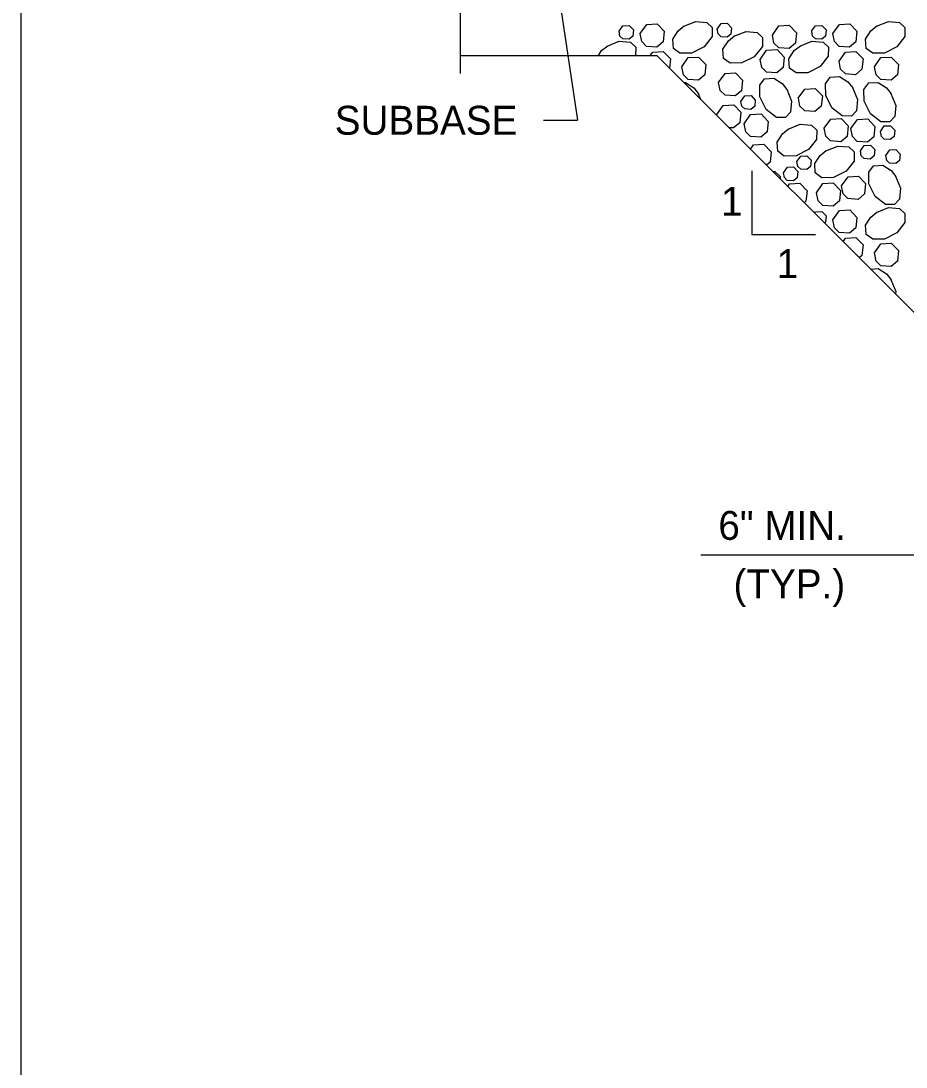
# Model space of a CAD drawing. Extents: x 638079 to 640019, y 297691 to 298879.
# Drawn here: x 639154 to 639245.9, y 298633.1 to 298741.7 of the extents above; entities that cross this region are included whole.
import ezdxf

# ---------------------------------------------------------------- set-up
doc = ezdxf.new("R2010")
doc.units = 0
doc.layers.add('1', color=7, linetype='Continuous')

msp = doc.modelspace()

# ---------------------------------------------------------------- linework, layer by layer
at = {"layer": '1'}
for p, q in [((639199.6, 298780.56), (639199.6, 298736.22)), ((639209.3, 298748.11), (639211.77, 298731.39)), ((639199.6, 298738.08), (639220.02, 298738.08)), ((639250.5, 298707.6), (639220.02, 298738.08)), ((639208.25, 298731.39), (639211.77, 298731.39)), ((639229.88, 298726.11), (639229.88, 298719.52)), ((639229.88, 298719.52), (639236.47, 298719.52)), ((639224.58, 298686.26), (639418.14, 298686.26))]:
    msp.add_line(p, q, dxfattribs=at)
for points in [[(639940.03, 298300.23), (639940.03, 298864.23), (639154.03, 298864.23), (639154.03, 298300.23), (639940.03, 298300.23), (639940.03, 298326.59), (639740.03, 298326.59), (639740.03, 298391.26), (639940.03, 298391.26), (639940.03, 298420.23), (639740.03, 298420.23), (639740.03, 298300.23), (639818.83, 298300.23), (639818.83, 298326.59), (639818.83, 298300.23), (639895.83, 298300.23), (639895.83, 298326.59), (639895.83, 298314.27), (639940.03, 298314.27)], [(639216.09, 298740.61), (639216.49, 298741.18), (639217.13, 298741.22), (639217.58, 298740.75), (639217.52, 298740.1), (639217.12, 298739.77), (639216.48, 298739.82), (639216.18, 298740.11), (639216.09, 298740.61)], [(639218.29, 298740.36), (639218.96, 298741.32), (639220.04, 298741.38), (639220.78, 298740.6), (639220.67, 298739.52), (639220.01, 298738.97), (639218.95, 298739.04), (639218.45, 298739.53), (639218.29, 298740.36)], [(639222.8, 298741.12), (639224.06, 298741.62), (639225.21, 298741.52), (639225.76, 298741), (639225.75, 298740.06), (639224.91, 298739), (639223.62, 298738.35), (639222.41, 298738.33), (639221.73, 298738.82), (639221.66, 298739.78), (639222.22, 298740.65), (639222.85, 298741.16)], [(639226.27, 298740.83), (639226.67, 298741.4), (639227.32, 298741.44), (639227.77, 298740.97), (639227.7, 298740.32), (639227.3, 298739.99), (639226.67, 298740.04), (639226.37, 298740.33), (639226.27, 298740.83)], [(639232, 298740.21), (639232.67, 298741.17), (639233.74, 298741.23), (639234.49, 298740.46), (639234.38, 298739.37), (639233.72, 298738.82), (639232.66, 298738.9), (639232.16, 298739.38), (639232, 298740.21)], [(639236.07, 298740.61), (639236.48, 298741.18), (639237.12, 298741.22), (639237.57, 298740.75), (639237.51, 298740.1), (639237.11, 298739.77), (639236.47, 298739.82), (639236.17, 298740.11), (639236.08, 298740.61)], [(639238.28, 298740.36), (639238.95, 298741.32), (639240.02, 298741.38), (639240.77, 298740.6), (639240.66, 298739.52), (639240, 298738.97), (639238.94, 298739.04), (639238.44, 298739.53), (639238.28, 298740.36)], [(639242.79, 298741.12), (639244.05, 298741.62), (639245.2, 298741.52), (639245.75, 298741), (639245.73, 298740.06), (639244.9, 298739), (639243.61, 298738.35), (639242.4, 298738.33), (639241.72, 298738.82), (639241.65, 298739.78), (639242.21, 298740.65), (639242.84, 298741.16)], [(639228.01, 298740.09), (639229.27, 298740.59), (639230.43, 298740.49), (639230.97, 298739.97), (639230.96, 298739.03), (639230.12, 298737.96), (639228.84, 298737.32), (639227.62, 298737.3), (639226.94, 298737.79), (639226.87, 298738.75), (639227.43, 298739.62), (639228.06, 298740.12)], [(639213.94, 298738.08), (639214.27, 298738.6), (639214.91, 298739.11)], [(639214.86, 298739.07), (639216.11, 298739.57), (639217.27, 298739.47), (639217.82, 298738.95), (639217.8, 298738.08)], [(639234.85, 298739.07), (639236.1, 298739.57), (639237.26, 298739.47), (639237.81, 298738.95), (639237.79, 298738.01), (639236.96, 298736.95), (639235.67, 298736.3), (639234.45, 298736.28), (639233.77, 298736.77), (639233.71, 298737.74), (639234.26, 298738.6), (639234.9, 298739.11)], [(639219.33, 298738.08), (639219.59, 298738.45), (639220.67, 298738.51), (639221.41, 298737.74), (639221.32, 298736.78)], [(639222.6, 298736.91), (639223.27, 298737.87), (639224.34, 298737.93), (639225.09, 298737.15), (639224.98, 298736.07), (639224.32, 298735.52), (639223.26, 298735.6), (639222.76, 298736.08), (639222.6, 298736.91)], [(639230.73, 298737.68), (639231.4, 298738.64), (639232.48, 298738.7), (639233.22, 298737.93), (639233.11, 298736.84), (639232.45, 298736.29), (639231.39, 298736.37), (639230.89, 298736.85), (639230.73, 298737.68)], [(639238.91, 298737.5), (639239.58, 298738.45), (639240.66, 298738.51), (639241.4, 298737.74), (639241.29, 298736.66), (639240.63, 298736.1), (639239.57, 298736.18), (639239.07, 298736.66), (639238.91, 298737.5)], [(639242.59, 298736.91), (639243.26, 298737.87), (639244.33, 298737.93), (639245.08, 298737.15), (639244.97, 298736.07), (639244.31, 298735.52), (639243.25, 298735.6), (639242.75, 298736.08), (639242.59, 298736.91)], [(639226.42, 298735.28), (639227.09, 298736.24), (639228.17, 298736.3), (639228.91, 298735.53), (639228.8, 298734.44), (639228.14, 298733.89), (639227.08, 298733.97), (639226.58, 298734.45), (639226.42, 298735.28)], [(639233.48, 298734.61), (639233.98, 298733.35), (639233.88, 298732.2), (639233.35, 298731.65), (639232.42, 298731.66), (639231.35, 298732.5), (639230.71, 298733.79), (639230.69, 298735), (639231.17, 298735.68), (639232.14, 298735.75), (639233, 298735.19), (639233.51, 298734.56)], [(639240.31, 298734.77), (639240.81, 298733.51), (639240.71, 298732.36), (639240.19, 298731.81), (639239.25, 298731.83), (639238.18, 298732.66), (639237.54, 298733.95), (639237.52, 298735.16), (639238, 298735.85), (639238.97, 298735.91), (639239.84, 298735.36), (639240.34, 298734.72)], [(639222.81, 298735.29), (639222.97, 298735.3), (639223.83, 298734.75), (639224.34, 298734.11)], [(639234.68, 298733.66), (639235.36, 298734.61), (639236.43, 298734.67), (639237.18, 298733.9), (639237.07, 298732.82), (639236.41, 298732.27), (639235.35, 298732.34), (639234.85, 298732.83), (639234.69, 298733.66)], [(639244.3, 298734.16), (639244.79, 298732.9), (639244.69, 298731.75), (639244.17, 298731.2), (639243.23, 298731.22), (639242.17, 298732.05), (639241.53, 298733.34), (639241.5, 298734.55), (639241.99, 298735.24), (639242.96, 298735.3), (639243.82, 298734.75), (639244.33, 298734.11)], [(639224.31, 298734.16), (639224.55, 298733.54)], [(639228.73, 298733.32), (639229.13, 298733.9), (639229.78, 298733.94), (639230.22, 298733.47), (639230.16, 298732.82), (639229.76, 298732.49), (639229.13, 298732.54), (639228.83, 298732.83), (639228.73, 298733.32)], [(639226.23, 298731.96), (639226.9, 298732.92), (639227.98, 298732.98), (639228.72, 298732.21), (639228.62, 298731.12), (639227.95, 298730.57), (639227.49, 298730.6)], [(639226.26, 298731.84), (639226.23, 298731.96)], [(639229.07, 298731.01), (639229.74, 298731.97), (639230.82, 298732.03), (639231.56, 298731.26), (639231.46, 298730.17), (639230.79, 298729.62), (639229.73, 298729.7), (639229.23, 298730.18), (639229.07, 298731.01)], [(639237.38, 298730.54), (639238.05, 298731.5), (639239.12, 298731.56), (639239.87, 298730.78), (639239.76, 298729.7), (639239.1, 298729.15), (639238.04, 298729.22), (639237.54, 298729.71), (639237.38, 298730.54)], [(639240.14, 298730.5), (639240.81, 298731.46), (639241.89, 298731.52), (639242.63, 298730.74), (639242.52, 298729.66), (639241.86, 298729.11), (639240.8, 298729.18), (639240.3, 298729.67), (639240.14, 298730.5)], [(639233.63, 298730.45), (639234.88, 298730.95), (639236.04, 298730.85), (639236.59, 298730.33), (639236.57, 298729.39), (639235.74, 298728.33), (639234.45, 298727.68), (639233.23, 298727.66), (639232.55, 298728.15), (639232.49, 298729.11), (639233.04, 298729.98), (639233.68, 298730.48)], [(639243.2, 298730.2), (639243.6, 298730.78), (639244.25, 298730.81), (639244.69, 298730.35), (639244.63, 298729.7), (639244.23, 298729.37), (639243.6, 298729.41), (639243.3, 298729.7), (639243.2, 298730.2)], [(639229.73, 298728.37), (639230.04, 298728.82), (639231.12, 298728.88), (639231.86, 298728.11), (639231.76, 298727.03), (639231.38, 298726.72)], [(639237.53, 298728.21), (639238.78, 298728.7), (639239.94, 298728.6), (639240.49, 298728.08), (639240.47, 298727.14), (639239.64, 298726.08), (639238.35, 298725.44), (639237.14, 298725.41), (639236.45, 298725.9), (639236.39, 298726.87), (639236.94, 298727.73), (639237.58, 298728.24)], [(639241.12, 298728.19), (639241.52, 298728.76), (639242.17, 298728.8), (639242.61, 298728.33), (639242.55, 298727.68), (639242.15, 298727.35), (639241.52, 298727.4), (639241.22, 298727.69), (639241.12, 298728.19)], [(639243.77, 298727.71), (639244.17, 298728.29), (639244.81, 298728.32), (639245.26, 298727.86), (639245.2, 298727.21), (639244.8, 298726.88), (639244.16, 298726.92), (639243.86, 298727.21), (639243.77, 298727.71)], [(639234.53, 298727.08), (639234.93, 298727.66), (639235.58, 298727.69), (639236.03, 298727.23), (639235.96, 298726.58), (639235.56, 298726.25), (639234.93, 298726.29), (639234.63, 298726.58), (639234.53, 298727.08)], [(639232.03, 298726.06), (639232.25, 298726.04), (639232.8, 298725.52), (639232.8, 298725.3)], [(639233.14, 298725.92), (639233.55, 298726.49), (639234.19, 298726.53), (639234.64, 298726.06), (639234.57, 298725.41), (639234.18, 298725.08), (639233.54, 298725.13), (639233.24, 298725.42), (639233.14, 298725.92)], [(639244.78, 298725.58), (639245.28, 298724.32), (639245.18, 298723.17), (639244.66, 298722.62), (639243.72, 298722.64), (639242.66, 298723.47), (639242.01, 298724.76), (639241.99, 298725.97), (639242.48, 298726.65), (639243.44, 298726.72), (639244.31, 298726.16), (639244.82, 298725.53)], [(639233.59, 298724.51), (639233.77, 298724.77), (639234.84, 298724.83), (639235.59, 298724.06), (639235.48, 298722.97), (639235.29, 298722.81)], [(639236.57, 298723.85), (639237.24, 298724.81), (639238.31, 298724.87), (639239.06, 298724.1), (639238.95, 298723.01), (639238.29, 298722.46), (639237.23, 298722.54), (639236.73, 298723.02), (639236.57, 298723.85)], [(639239.17, 298724.56), (639239.85, 298725.51), (639240.92, 298725.57), (639241.67, 298724.8), (639241.56, 298723.72), (639240.89, 298723.16), (639239.84, 298723.24), (639239.34, 298723.72), (639239.17, 298724.56)], [(639236.38, 298721.72), (639236.48, 298721.87), (639237.12, 298721.9), (639237.57, 298721.44), (639237.51, 298720.79), (639237.4, 298720.7)], [(639238.28, 298721.04), (639238.95, 298722), (639240.02, 298722.06), (639240.77, 298721.29), (639240.66, 298720.2), (639240, 298719.65), (639238.94, 298719.73), (639238.44, 298720.21), (639238.28, 298721.04)], [(639242.79, 298721.81), (639244.05, 298722.31), (639245.2, 298722.21), (639245.75, 298721.69), (639245.73, 298720.75), (639244.9, 298719.68), (639243.61, 298719.04), (639242.4, 298719.02), (639241.72, 298719.5), (639241.65, 298720.47), (639242.21, 298721.33), (639242.84, 298721.84)], [(639239.33, 298718.77), (639239.58, 298719.14), (639240.66, 298719.2), (639241.4, 298718.43), (639241.29, 298717.34), (639241, 298717.1)], [(639242.59, 298717.6), (639243.26, 298718.55), (639244.33, 298718.61), (639245.08, 298717.84), (639244.97, 298716.76), (639244.31, 298716.2), (639243.25, 298716.28), (639242.75, 298716.76), (639242.59, 298717.6)], [(639242.16, 298715.93), (639242.96, 298715.99), (639243.82, 298715.43), (639244.33, 298714.8)], [(639244.3, 298714.85), (639244.79, 298713.59), (639244.77, 298713.32)]]:
    msp.add_lwpolyline(points, dxfattribs=at)

# ---------------------------------------------------------------- texts
for s, p in [('SUBBASE', (639186.59, 298729.87)), ('1', (639226.67, 298721.46)), ('1', (639232.44, 298715)), ('6" MIN.', (639226.39, 298687.83)), ('(TYP.)', (639227.96, 298681.76))]:
    msp.add_text(s, height=3, dxfattribs=at).set_placement(p)

doc.saveas('drawing.dxf')
